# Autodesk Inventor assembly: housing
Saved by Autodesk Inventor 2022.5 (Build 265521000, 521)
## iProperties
Created: 2024-12
Part Number: housing
Document SubType Name: Assembly
Designer: AdminForWorker
Title: housing
Author: AdminForWorker
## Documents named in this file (2)
- c:\worker\convert-fusion-r05-cosv3\tmp\job-1\35\temp\files\545dca92-a972-481a-9197-dd1a1176500e\housing.iam
- c:\worker\convert-fusion-r05-cosv3\tmp\job-1\35\temp\files\545dca92-a972-481a-9197-dd1a1176500e\shell.ipt
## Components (1 placed, 1 different names)
1. shell:1
